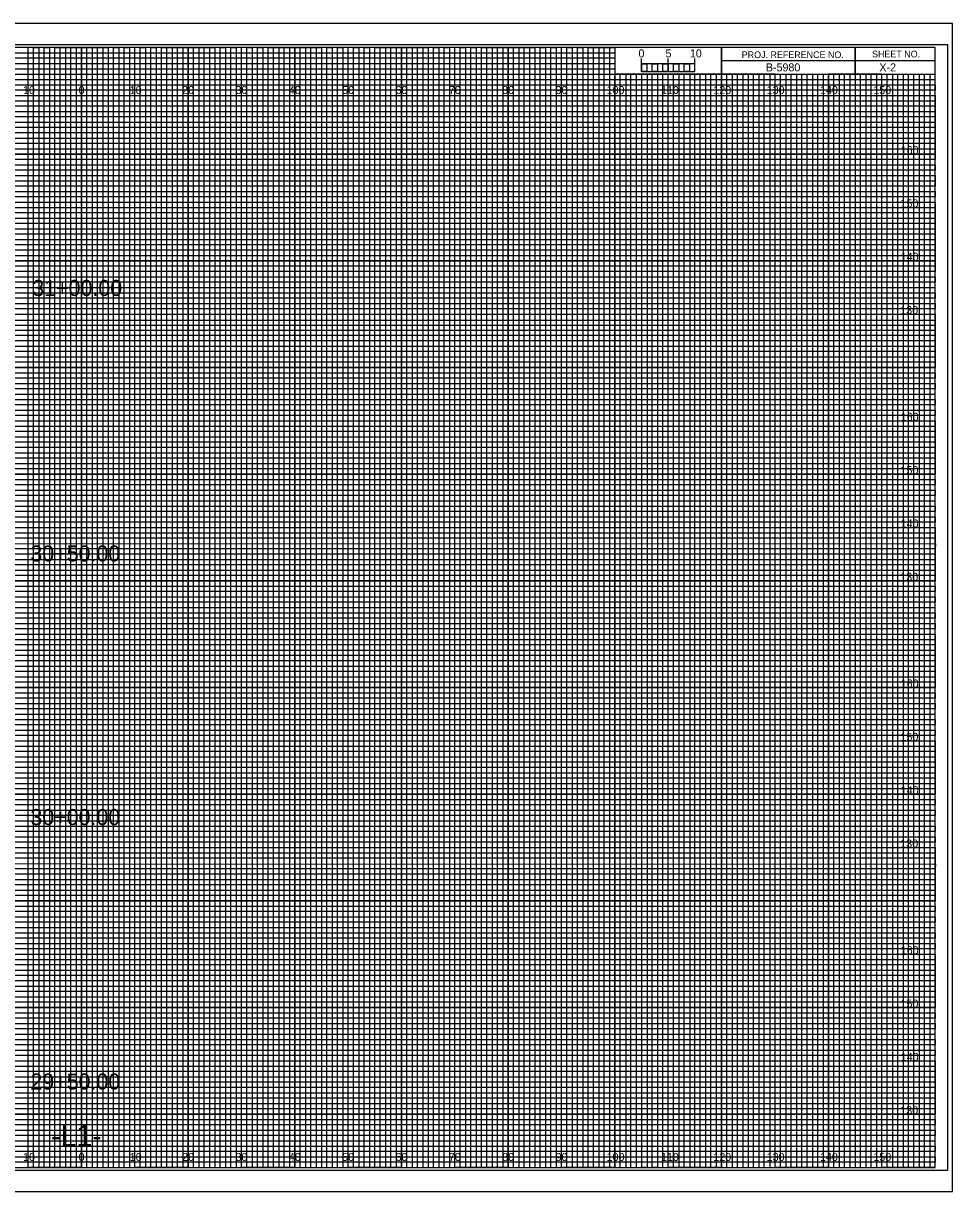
# Model space of a CAD drawing. Extents: x -13 to 323, y -5 to 3294.
# Drawn here: x 149.1 to 323.3, y 215.5 to 434.5 of the extents above; entities that cross this region are included whole.
import ezdxf

# ---------------------------------------------------------------- set-up
doc = ezdxf.new("R2010")
doc.units = 0
for name, color, linetype in [('Prop XS Alignment Label', 7, 'Continuous'), ('Prop XS Bar Scale Labels', 7, 'Continuous'), ('Prop XS Elevation Labels', 7, 'Continuous'), ('Prop XS Offset Labels', 7, 'Continuous'), ('Prop XS Project Number', 7, 'Continuous'), ('Prop XS Sheet Number', 7, 'Continuous'), ('Prop XS Station Labels', 7, 'Continuous'), ('Sheet Cross Section CELL', 7, 'Continuous'), ('Sheet Cross Section Grid Major CELL', 7, 'Continuous'), ('Sheet Cross Section Grid Middle CELL', 7, 'Continuous'), ('Sheet Cross Section Grid Minor 1 CELL', 7, 'Continuous'), ('Sheet Cross Section Grid Minor 2 CELL', 7, 'Continuous'), ('Sheet Cross Section Scale CELL', 7, 'Continuous'), ('Sheet Cutting Line CELL', 7, 'Continuous'), ('Sheet DOT Grid CELL', 7, 'Continuous'), ('Sheet Plot Border Inside CELL', 7, 'Continuous'), ('Sheet Plot Border Outside CELL', 7, 'Continuous')]:
    doc.layers.add(name, color=color, linetype=linetype)

msp = doc.modelspace()

# ---------------------------------------------------------------- linework, layer by layer
at = {"layer": 'Sheet Cross Section CELL'}
for p, q in [((305, 430), (305, 425)), ((305, 425), (305, 430)), ((280, 427.5), (280, 425)), ((320, 427.49), (280, 427.49)), ((280, 425), (320, 425))]:
    msp.add_line(p, q, dxfattribs=at)
for points in [[(320, 430), (0, 430), (0, 220), (320, 220)], [(280, 430), (260, 430), (260, 425.03), (280, 425.03)], [(320, 430), (280, 430), (280, 425), (320, 425)]]:
    msp.add_lwpolyline(points, close=True, dxfattribs=at)
at = {"layer": 'Sheet Cross Section Grid Major CELL'}
for p, q in [((150, 430), (140, 430)), ((150, 220), (150, 430)), ((170, 430), (160, 430)), ((160, 430), (160, 220)), ((170, 220), (170, 430)), ((190, 430), (180, 430)), ((180, 430), (180, 220)), ((190, 220), (190, 430)), ((210, 430), (200, 430)), ((200, 430), (200, 220)), ((210, 220), (210, 430)), ((230, 430), (220, 430)), ((220, 430), (220, 220)), ((230, 220), (230, 430)), ((250, 430), (240, 430)), ((240, 430), (240, 220)), ((250, 220), (250, 430)), ((260, 430), (260, 220)), ((270, 220), (270, 425)), ((290, 425), (280, 425)), ((280, 425), (280, 220)), ((290, 220), (290, 425)), ((310, 425), (300, 425)), ((300, 425), (300, 220)), ((310, 220), (310, 425)), ((160, 220), (150, 220)), ((180, 220), (170, 220)), ((200, 220), (190, 220)), ((220, 220), (210, 220)), ((240, 220), (230, 220)), ((260, 220), (250, 220)), ((280, 220), (270, 220)), ((300, 220), (290, 220)), ((320, 220), (310, 220)), ((320, 220), (320, 220))]:
    msp.add_line(p, q, dxfattribs=at)
for points in [[(0, 420), (320, 420), (320, 410), (0, 410)], [(0, 400), (320, 400), (320, 390), (0, 390)], [(0, 380), (320, 380), (320, 370), (0, 370)], [(0, 360), (320, 360), (320, 350), (0, 350)], [(0, 340), (320, 340), (320, 330), (0, 330)], [(0, 320), (320, 320), (320, 310), (0, 310)], [(0, 300), (320, 300), (320, 290), (0, 290)], [(0, 280), (320, 280), (320, 270), (0, 270)], [(0, 260), (320, 260), (320, 250), (0, 250)], [(0, 240), (320, 240), (320, 230), (0, 230)]]:
    msp.add_lwpolyline(points, dxfattribs=at)
at = {"layer": 'Sheet Cross Section Grid Middle CELL'}
for points in [[(145, 220), (155, 220), (155, 430), (165, 430), (165, 220), (175, 220), (175, 430), (185, 430), (185, 220), (195, 220), (195, 430), (205, 430), (205, 220), (215, 220), (215, 430), (225, 430), (225, 220), (235, 220), (235, 430), (245, 430), (245, 220), (255, 220), (255, 430), (259.93, 430), (260, 430), (260, 425), (264.99, 425), (264.99, 220), (275, 220), (275, 425), (285, 425), (285, 220), (295, 220), (295, 425), (305, 425), (305, 220), (315, 220), (315, 425)], [(0, 425), (275, 425)], [(0, 405), (320, 405), (320, 415), (0, 415)], [(0, 385), (320, 385), (320, 395), (0, 395)], [(0, 365), (320, 365), (320, 375), (0, 375)], [(0, 345), (320, 345), (320, 355), (0, 355)], [(0, 325), (320, 325), (320, 335), (0, 335)], [(0, 305), (320, 305), (320, 315), (0, 315)], [(0, 285), (320, 285), (320, 295), (0, 295)], [(0, 265), (320, 265), (320, 275), (0, 275)], [(0, 245), (320, 245), (320, 255), (0, 255)], [(0, 225), (320, 225), (320, 235), (0, 235)]]:
    msp.add_lwpolyline(points, dxfattribs=at)
at = {"layer": 'Sheet Cross Section Grid Minor 1 CELL'}
for p, q in [((0, 429), (260, 429)), ((260, 427.98), (0, 427.98)), ((260, 429), (260, 427.98)), ((0, 427), (260, 427)), ((260, 425.89), (0, 425.89)), ((260, 427), (260, 425.89)), ((0, 424), (320, 424))]:
    msp.add_line(p, q, dxfattribs=at)
for points in [[(0, 423), (270, 423), (320, 423), (320, 422), (0, 422)], [(0, 421), (320, 421), (320, 419), (0, 419)], [(0, 418), (320, 418), (320, 417), (0, 416.98)], [(0, 416), (320, 416), (320, 414), (0, 414)], [(0, 413), (320, 413), (320, 412), (0, 412)], [(0, 411), (320, 411), (320, 409), (0, 409)], [(0, 408), (320, 408), (320, 407), (0, 407)], [(0, 406), (320, 406), (320, 404), (0, 404)], [(0, 403), (320, 403), (320, 402), (0, 402)], [(0, 401), (320, 401), (320, 399), (0, 399)], [(0, 398), (320, 398), (320, 397), (0, 397)], [(0, 396), (320, 396), (320, 393.95), (320, 393), (320, 392), (0, 392)], [(0, 394), (320, 394), (320, 393), (0, 393)], [(0, 391), (320, 391), (320, 389), (0, 389.03)], [(0, 389.03), (320, 389), (320, 388), (0, 388)], [(0, 387), (320, 387), (320, 386), (0, 386)], [(0, 384), (320, 384), (320, 383), (0, 383)], [(0, 382), (320, 382), (320, 381), (0, 381)], [(-0.07, 378.89), (320, 378.89), (320, 377.88), (-0.07, 377.88)], [(0, 377), (320, 377), (320, 376), (0, 376)], [(0, 374), (320, 374), (320, 373), (0, 373)], [(0, 372), (320, 372), (320, 371), (0, 371)], [(0, 369), (320, 369), (320, 368), (0, 368)], [(0, 367), (320, 367), (320, 366), (0, 366)], [(0, 364), (320, 364), (320, 363), (0, 363)], [(0, 362), (320, 362), (320, 361), (0, 361)], [(0, 359), (320, 359), (319.99, 357.98), (0, 358)], [(0, 357), (320, 357), (320, 356), (0, 356)], [(0, 354), (320, 354), (320, 353), (0, 353)], [(0, 352), (320, 352), (320, 351), (0, 351)], [(0, 349), (320, 349), (320, 348), (0, 348)], [(0, 347), (320, 347), (320, 346), (0, 346)], [(0, 344), (320, 344), (320, 343), (0, 343)], [(0, 342), (320, 342), (320, 341), (0, 341)], [(0, 339), (320, 339), (320, 338), (0, 338)], [(0, 336.99), (320.07, 336.91), (320, 336), (0, 336)], [(0, 334), (320, 334), (320, 333), (0, 333)], [(0, 332), (320, 332), (320, 331), (0, 331)], [(0, 329), (320, 329), (320, 328), (0, 328)], [(0, 327), (320, 327), (320, 326), (0, 326)], [(0, 324), (320, 324), (320, 323), (0, 323)], [(0, 322), (320, 322), (320, 321), (0, 321)], [(0, 319), (320, 319), (320, 318), (0, 318)], [(0, 317), (320, 317), (320, 316), (0, 316)], [(0, 314), (320, 314), (320, 313), (0, 313)], [(0, 312), (320, 312), (320, 311), (0, 311)], [(0, 309), (320, 309), (320, 308), (0, 308)], [(0, 307), (320, 307), (320, 306), (0, 306)], [(0, 304), (320, 304), (320, 303), (0, 303)], [(0, 302), (320, 302), (320, 301), (0, 301)], [(0, 299), (320, 299), (319.99, 297.98), (0, 298)], [(0, 297), (320, 297), (320, 296), (0, 296)], [(0, 294), (320, 294), (320, 293), (0, 293)], [(0, 292), (320, 292), (320, 291), (0, 291)], [(0, 289), (320, 289), (320, 288), (0, 288)], [(0, 287), (320, 287), (320, 286), (0, 286)], [(0, 284), (320, 284), (320, 283), (0, 283)], [(0, 282), (320, 282), (320, 281), (0, 281)], [(0, 279), (320, 279), (320, 278), (0, 278)], [(0, 276.99), (320.07, 276.91), (320, 276), (0, 276)], [(0, 274), (320, 274), (320, 273), (0, 273)], [(0, 272), (320, 272), (320, 271), (0, 271)], [(0, 269), (320, 269), (320, 268), (0, 268)], [(0, 267), (320, 267), (320, 266), (0, 266)], [(0, 264), (320, 264), (320, 263), (0, 263)], [(0, 262), (320, 262), (320, 261), (0, 261)], [(0, 259), (320, 259), (320, 258), (0, 258)], [(0, 257), (320, 257), (320, 256), (0, 256)], [(0, 254), (320, 254), (320, 253), (0, 253)], [(0, 252), (320, 252), (320, 251), (0, 251)], [(0, 249), (320, 249), (320, 248), (0, 248)], [(0, 247), (320, 247), (320, 246), (0, 246)], [(0, 244), (320, 244), (320, 243), (0, 243)], [(0, 242), (320, 242), (320, 241), (0, 241)], [(0, 239), (320, 239), (320, 238), (0, 238)], [(0, 237), (320, 237), (320, 236), (0, 236)], [(0, 234), (320, 234), (320, 233), (0, 233)], [(0, 232), (320, 232), (320, 231), (0, 231)], [(0, 229), (320, 229), (320, 228), (0, 228)], [(0, 227), (320, 227), (320, 226), (0, 226)], [(0, 224), (320, 224), (320, 223), (0, 223)], [(0, 222), (320, 222), (320, 221), (0, 221)]]:
    msp.add_lwpolyline(points, dxfattribs=at)
at = {"layer": 'Sheet Cross Section Grid Minor 2 CELL'}
for p, q in [((267, 425), (266.01, 425)), ((266.01, 425), (266.01, 220)), ((267, 220), (267, 425)), ((269, 425), (268, 425)), ((268, 425), (268, 220)), ((269, 220), (269, 425)), ((266.01, 220), (265, 220)), ((268, 220), (267, 220))]:
    msp.add_line(p, q, dxfattribs=at)
for points in [[(150, 220), (151, 220), (151, 430), (152, 430), (152, 220)], [(152, 220), (153, 220), (153, 430), (154, 430), (154, 220)], [(155, 220), (156, 220), (156, 430), (157, 430), (157, 220)], [(157, 220), (158, 220), (158, 430), (159, 430), (159, 220)], [(160, 220), (161, 220), (161, 430), (162, 430), (162, 220)], [(162, 220), (163, 220), (163, 430), (164, 430), (164, 220)], [(165, 220), (166, 220), (166, 430), (167, 430), (167, 220)], [(167, 220), (168, 220), (168, 430), (169, 430), (169, 220)], [(170, 220), (171, 220), (171, 430), (172, 430), (172, 220)], [(172, 220), (173, 220), (173, 430), (174, 430), (174, 220)], [(175, 220), (176, 220), (176, 430), (177, 430), (177, 220)], [(177, 220), (178, 220), (178, 430), (179, 430), (179, 220)], [(180, 220), (181, 220), (181, 430), (182, 430), (182, 220)], [(182, 220), (183, 220), (183, 430), (184, 430), (184, 220)], [(185, 220), (186, 220), (186, 430), (187, 430), (187, 220)], [(187, 220), (188, 220), (188, 430), (189, 430), (189, 220)], [(190, 220), (191, 220), (191, 430), (192, 430), (192, 220)], [(192, 220), (193, 220), (193, 430), (194, 430), (194, 220)], [(195, 220), (196, 220), (196, 430), (197, 430), (197, 220)], [(197, 220), (198, 220), (198, 430), (199, 430), (199, 220)], [(200, 220), (201, 220), (201, 430), (202, 430), (202, 220)], [(202, 220), (203, 220), (203, 430), (204, 430), (204, 220)], [(205, 220), (206, 220), (206, 430), (207, 430), (207, 220)], [(207, 220), (208, 220), (208, 430), (209, 430), (209, 220)], [(210, 220), (211, 220), (211, 430), (212, 430), (212, 220)], [(212, 220), (213, 220), (213, 430), (214, 430), (214, 220)], [(215, 220), (216, 220), (216, 430), (217, 430), (217, 220)], [(217, 220), (218, 220), (218, 430), (219, 430), (219, 220)], [(220, 220), (221, 220), (221, 430), (222, 430), (222, 220)], [(222, 220), (223, 220), (223, 430), (224, 430), (224, 220)], [(225, 220), (226, 220), (226, 430), (227, 430), (227, 220)], [(227, 220), (228, 220), (228, 430), (229, 430), (229, 220)], [(230, 220), (231, 220), (231, 430), (232, 430), (232, 220)], [(232, 220), (233, 220), (233, 430), (234, 430), (234, 220)], [(235, 220), (236, 220), (236, 430), (237, 430), (237, 220)], [(237, 220), (238, 220), (238, 430), (239, 430), (239, 220)], [(240, 220), (241, 220), (241, 430), (242, 430), (242, 220)], [(242, 220), (243, 220), (243, 430), (244, 430), (244, 220)], [(245, 220), (246, 220), (246, 430), (247, 430), (247, 220)], [(247, 220), (248, 220), (248, 430), (249, 430), (249, 220)], [(250, 220), (251, 220), (251, 430), (252, 430), (252, 220)], [(252, 220), (253, 220), (253, 430), (254, 430), (254, 220)], [(255, 220), (256, 220), (256, 430), (257, 430), (257, 220)], [(257, 220), (258, 220), (258, 430), (259, 430), (259, 220)], [(260, 220), (261, 220), (261, 425), (262.02, 425), (262.02, 220)], [(262, 220), (263, 220), (263, 425), (263.99, 425), (263.99, 220)], [(270, 220), (270.98, 220), (270.98, 425), (272, 425), (272, 220)], [(272, 220), (273, 220), (273, 425), (274.05, 425), (274.05, 220)], [(275, 220), (276, 220), (276, 425), (277, 425), (277, 220)], [(277, 220), (278, 220), (278, 425), (279, 425), (279, 220)], [(280, 220), (281, 220), (281, 425), (282, 425), (282, 220)], [(282, 220), (283, 220), (283, 425), (284, 425), (284, 220)], [(285, 220), (286, 220), (286, 425), (287, 425), (287, 220)], [(287, 220), (288, 220), (288, 425), (289, 425), (289, 220)], [(290, 220), (291, 220), (291, 425), (292, 425), (292, 220)], [(292, 220), (293, 220), (293, 425), (294, 425), (294, 220)], [(295, 220), (296, 220), (296, 425), (297, 425), (297, 220)], [(297, 220), (298, 220), (298, 425), (299, 425), (299, 220)], [(300, 220), (301, 220), (301, 425), (302, 425), (302, 220)], [(302, 220), (303, 220), (303, 425), (304, 425), (304, 220)], [(305, 220), (306, 220), (306, 425), (307, 425), (307, 220)], [(307, 220), (308, 220), (308, 425), (309, 425), (309, 220)], [(310, 220), (311, 220), (311, 425), (312, 425), (312, 220)], [(312, 220), (313, 220), (313, 425), (314, 425), (314, 220)], [(315, 220), (316, 220), (316, 425), (317, 425), (317, 220)], [(317, 220), (318, 220), (318, 425), (319, 425), (319, 220)]]:
    msp.add_lwpolyline(points, dxfattribs=at)
at = {"layer": 'Sheet Cross Section Scale CELL'}
for p, q in [((265, 425.49), (265, 427.9)), ((265, 426.9), (265, 427.9)), ((270, 425.49), (270, 427.9)), ((275, 425.49), (275, 427.9)), ((275, 426.9), (275, 427.9))]:
    msp.add_line(p, q, dxfattribs=at)
for points in [[(275, 426.9), (265, 426.9), (265, 425.49), (275, 425.49)], [(265, 426.9), (266, 426.9), (266, 425.49), (265, 425.49)], [(267, 426.9), (268, 426.9), (268, 425.49), (267, 425.49)], [(269, 426.9), (270, 426.9), (270, 425.49), (269, 425.49)], [(271, 426.9), (272, 426.9), (272, 425.49), (271, 425.49)], [(273, 426.9), (274, 426.9), (274, 425.49), (273, 425.49)]]:
    msp.add_lwpolyline(points, close=True, dxfattribs=at)
at = {"layer": 'Sheet Cutting Line CELL'}
for p, q in [((323.3, 434.5), (-13.4, 434.5)), ((-13.4, 215.5), (323.3, 215.5))]:
    msp.add_line(p, q, dxfattribs=at)
at = {"layer": 'Sheet DOT Grid CELL'}
for p, q in [((150, 220), (150, 430)), ((160, 220), (160, 430)), ((170, 220), (170, 430)), ((180, 220), (180, 430)), ((190, 220), (190, 430)), ((200, 220), (200, 430)), ((210, 220), (210, 430)), ((220, 220), (220, 430)), ((230, 220), (230, 430)), ((240, 220), (240, 430)), ((250, 220), (250, 430)), ((260, 220), (260, 424.69)), ((270, 220), (270, 424.69)), ((280, 220), (280, 424.69)), ((290, 220), (290, 424.69)), ((300, 220), (300, 424.69)), ((310, 220), (310, 424.69)), ((0, 420), (320, 420)), ((0, 410), (320, 410)), ((0, 400), (320, 400)), ((0, 390), (320, 390)), ((0, 380), (320, 380)), ((0, 370), (320, 370)), ((0, 360), (320, 360)), ((0, 350), (320, 350)), ((0, 340), (320, 340)), ((0, 330), (320, 330)), ((0, 320), (320, 320)), ((0, 310), (320, 310)), ((0, 300), (320, 300)), ((0, 290), (320, 290)), ((0, 280), (320, 280)), ((0, 270), (320, 270)), ((0, 260), (320, 260)), ((0, 250), (320, 250)), ((0, 240), (320, 240)), ((0, 230), (320, 230))]:
    msp.add_line(p, q, dxfattribs=at)
at = {"layer": 'Sheet Plot Border Inside CELL'}
msp.add_lwpolyline([(-10.8, 219.5), (322.4, 219.5), (322.4, 430.5), (-10.8, 430.5)], close=True, dxfattribs=at)
at = {"layer": 'Sheet Plot Border Outside CELL'}
msp.add_lwpolyline([(-13.4, 215.5), (323.3, 215.5), (323.3, 434.5), (-13.4, 434.5)], close=True, dxfattribs=at)

# ---------------------------------------------------------------- texts
at = {"layer": 'Prop XS Alignment Label'}
msp.add_text('-L1-', height=4, dxfattribs=at).set_placement((154.28, 224))
at = {"layer": 'Prop XS Bar Scale Labels'}
for s, p in [('5', (269.47, 428.12)), ('10', (274.04, 428.12))]:
    msp.add_text(s, height=1.5, dxfattribs=at).set_placement(p)
at = {"layer": 'Prop XS Elevation Labels'}
for s, p in [('160', (313.57, 410)), ('150', (313.52, 400)), ('140', (313.57, 390)), ('130', (313.49, 380)), ('160', (313.57, 360)), ('150', (313.52, 350)), ('140', (313.57, 340)), ('130', (313.49, 330)), ('160', (313.57, 310)), ('150', (313.52, 300)), ('140', (313.57, 290)), ('130', (313.49, 280)), ('160', (313.57, 260)), ('150', (313.52, 250)), ('140', (313.57, 240)), ('130', (313.49, 230))]:
    msp.add_text(s, height=1.5, dxfattribs=at).set_placement(p)
at = {"layer": 'Prop XS Offset Labels'}
for s, p in [('10', (149.04, 421.25)), ('0', (159.45, 421.25)), ('0', (159.45, 421.25)), ('10', (169.04, 421.25)), ('20', (178.86, 421.25)), ('30', (188.86, 421.25)), ('40', (198.86, 421.25)), ('50', (208.86, 421.25)), ('60', (218.86, 421.25)), ('70', (228.86, 421.25)), ('80', (238.86, 421.25)), ('90', (248.86, 421.25)), ('100', (258.44, 421.25)), ('110', (268.62, 421.25)), ('120', (278.44, 421.25)), ('130', (288.44, 421.25)), ('140', (298.44, 421.25)), ('150', (308.44, 421.25)), ('10', (149.04, 221.25)), ('0', (159.45, 221.25)), ('0', (159.45, 221.25)), ('10', (169.04, 221.25)), ('20', (178.86, 221.25)), ('30', (188.86, 221.25)), ('40', (198.86, 221.25)), ('50', (208.86, 221.25)), ('60', (218.86, 221.25)), ('70', (228.86, 221.25)), ('80', (238.86, 221.25)), ('90', (248.86, 221.25)), ('100', (258.44, 221.25)), ('110', (268.62, 221.25)), ('120', (278.44, 221.25)), ('130', (288.44, 221.25)), ('140', (298.44, 221.25)), ('150', (308.44, 221.25))]:
    msp.add_text(s, height=1.5, dxfattribs=at).set_placement(p)
at = {"layer": 'Prop XS Project Number'}
msp.add_text('B-5980', height=1.5, dxfattribs=at).set_placement((288.28, 425.5))
at = {"layer": 'Prop XS Sheet Number'}
msp.add_text('X-2', height=1.5, dxfattribs=at).set_placement((309.57, 425.5))
at = {"layer": 'Prop XS Station Labels'}
for s, p in [('31+00.00', (150.77, 383.4)), ('30+50.00', (150.41, 333.63)), ('30+00.00', (150.41, 284.22)), ('29+50.00', (150.41, 234.64))]:
    msp.add_text(s, height=3, dxfattribs=at).set_placement(p)
at = {"layer": 'Sheet Cross Section CELL'}
for s, p in [('PROJ. REFERENCE NO.', (283.77, 427.99)), ('SHEET NO.', (308.19, 428.12))]:
    msp.add_text(s, height=1.25, dxfattribs=at).set_placement(p)
at = {"layer": 'Sheet Cross Section Scale CELL'}
msp.add_text('0', height=1.5, dxfattribs=at).set_placement((264.41, 428.12))

doc.saveas('drawing.dxf')
